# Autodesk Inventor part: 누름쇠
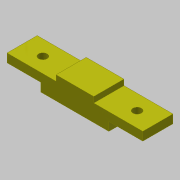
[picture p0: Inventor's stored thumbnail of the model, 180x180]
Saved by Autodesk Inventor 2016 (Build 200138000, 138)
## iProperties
Created: 2019-06
Part Number: 누름쇠
Material: 스테인리스강
Document SubType Name: Modeling
Designer: mduedu
Density: 8.08 g/cm^3
Appearance: 노란색
Mass: 69.4303 g
Surface Area: 38.4362 cm^2
Volume: 8.59286 cm^3
Author: mduedu
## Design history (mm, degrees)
sketch "스케치1"
  geometry: L1 (-36, 0)-(36, 0); L2 (36, 0)-(36, 12); L3 (36, 12)-(-36, 12); L4 (-36, 12)-(-36, 0); 2 further points
  constraints: 8 end point, 2 parallel, 1 coincident, 1 horizontal, 1 midpoint, 1 perpendicular
  dimensions: "d0" = 72 distance of L1.start L1.end; "d2" = 12 distance of L1.end L2.end
extrude "돌출1" new body sketch "스케치1" stored distance "d3" = 16; taper "d4" = 0 deg
sketch "스케치2"
  geometry: L1 (-36, 0)-(36, 0) reference; L2 (36, 0)-(36, 12) reference; L3 (36, 12)-(-36, 12) reference; L4 (-36, 12)-(-36, 0) reference; L5 (0, 0)-(0, 12); L6 (-36, 0)-(-18, 0); L7 (-18, 0)-(-18, 4.5); L8 (-18, 4.5)-(-36, 4.5); L9 (-36, 4.5)-(-36, 0); L10 (-36, 12)-(-10, 12); L11 (-10, 12)-(-10, 9); L12 (-10, 9)-(-36, 9); L13 (-36, 9)-(-36, 12); L14 (36, 12)-(36, 0); L15 (36, 0)-(18, 0); L16 (18, 0)-(18, 4.5); L17 (18, 4.5)-(36, 4.5); L18 (36, 4.5)-(36, 0); L19 (36, 12)-(10, 12); L20 (10, 12)-(10, 9); L21 (10, 9)-(36, 9); L22 (36, 9)-(36, 12)
  constraints: 36 end point, 6 symmetric about line, 4 parallel, 2 horizontal, 2 perpendicular, 1 midpoint
  dimensions: "d5" = 18 distance between parallel lines of L5 L7; "d7" = 4.5 distance between parallel lines of L1 L8; "d8" = 10 distance between parallel lines of L5 L11; "d9" = 3 distance between parallel lines of L12 L3
extrude "돌출2" cut sketch "스케치2" stored distance "d10" = 16; taper "d11" = 0 deg
sketch "스케치3"
  geometry: L1 (26, 0)-(26, 16) reference; L2 (0, 16)-(26, 16) reference; L3 (0, 0)-(0, 16) reference; L4 (26, 0)-(0, 0) reference; L5 (46, 0)-(26, 0) reference; L6 (46, 16)-(46, 0) reference; L7 (46, 16)-(72, 16) reference; L8 (72, 16)-(72, 0) reference; L9 (72, 0)-(46, 0) reference; L10 (26, 16)-(46, 16) reference; L11 (36, 16)-(36, 0); C1 r 2.25 at (11, 8); C2 r 2.25 at (61, 8); 1 further point
  constraints: 2 centre point, 2 end point, 2 midpoint, 1 horizontal alignment, 1 symmetric about line, 1 other
  dimensions: "d12" = 4.5 diameter of C1; "d13" = 25 distance of C1.centre point (36, 8)
extrude "돌출3" cut sketch "스케치3" stored distance "d14" = 16; taper "d15" = 0 deg
node "솔리드1"
node "투영된 루프1"
node "절단 모서리 투영1"
